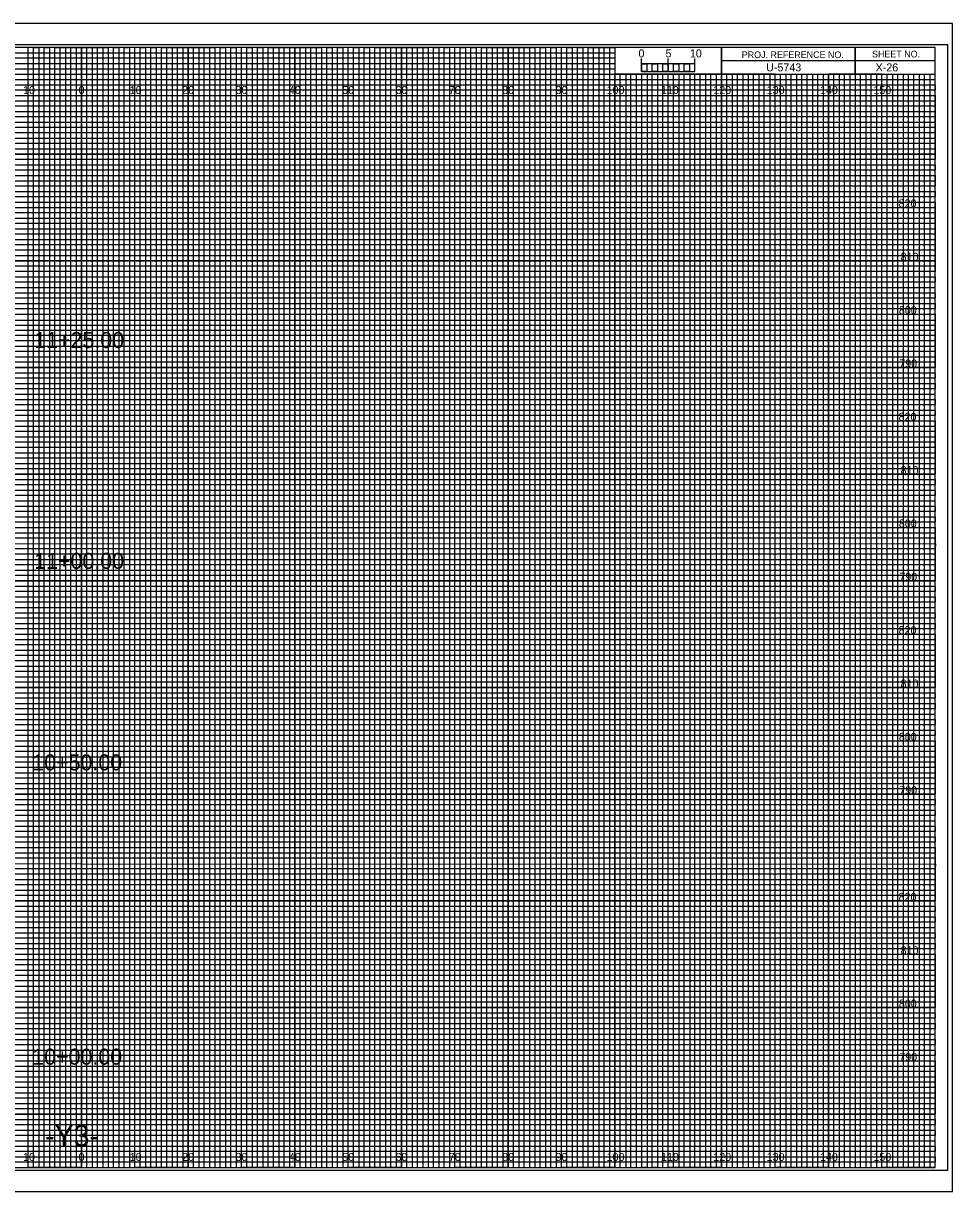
# Model space of a CAD drawing. Extents: x -13 to 323, y -4 to 214.
# Drawn here: x 149.1 to 323.3, y -4.5 to 214.5 of the extents above; entities that cross this region are included whole.
import ezdxf

# ---------------------------------------------------------------- set-up
doc = ezdxf.new("R2010")
doc.units = 0
for name, color, linetype in [('Exist Cross Section Cell', 7, 'Continuous'), ('Exist XS Ground Line', 7, 'Continuous'), ('Prop CMT Conc Surface', 7, 'Continuous'), ('Prop CMT Concrete Structures', 7, 'Continuous'), ('Prop CMT Pvmt Course 1', 7, 'Continuous'), ('Prop CMT Pvmt Course 1 CG', 7, 'Continuous'), ('Prop CMT Pvmt Course 2', 7, 'Continuous'), ('Prop CMT Pvmt Course 3', 7, 'Continuous'), ('Prop CMT Pvmt Surface', 7, 'Continuous'), ('Prop CMT Slope Grass', 7, 'Continuous'), ('Prop CMT Subgrade Earthwork', 7, 'Continuous'), ('Prop XS Hydro Elevations', 7, 'Continuous'), ('Prop XS SE Text', 7, 'Continuous'), ('Prop XS Side Slope Text', 7, 'Continuous'), ('Scratch_Level_4', 7, 'Continuous'), ('Scratch_Level_7', 7, 'Continuous'), ('Scratch_Level_9', 7, 'Continuous')]:
    doc.layers.add(name, color=color, linetype=linetype)

msp = doc.modelspace()

# ---------------------------------------------------------------- linework, layer by layer
at = {"layer": 'Exist XS Ground Line'}
for p, q in [((150, 210), (140, 210)), ((150, 0), (150, 210)), ((170, 210), (160, 210)), ((160, 210), (160, 0)), ((170, 0), (170, 210)), ((190, 210), (180, 210)), ((180, 210), (180, 0)), ((190, 0), (190, 210)), ((210, 210), (200, 210)), ((200, 210), (200, 0)), ((210, 0), (210, 210)), ((230, 210), (220, 210)), ((220, 210), (220, 0)), ((230, 0), (230, 210)), ((250, 210), (240, 210)), ((240, 210), (240, 0)), ((250, 0), (250, 210)), ((260, 210), (260, 0)), ((270, 0), (270, 205)), ((290, 205), (280, 205)), ((280, 205), (280, 0)), ((290, 0), (290, 205)), ((310, 205), (300, 205)), ((300, 205), (300, 0)), ((310, 0), (310, 205)), ((160, 0), (150, 0)), ((180, 0), (170, 0)), ((200, 0), (190, 0)), ((220, 0), (210, 0)), ((240, 0), (230, 0)), ((260, 0), (250, 0)), ((280, 0), (270, 0)), ((300, 0), (290, 0)), ((320, 0), (310, 0)), ((320, 0), (320, 0))]:
    msp.add_line(p, q, dxfattribs=at)
for points in [[(0, 200), (320, 200), (320, 190), (0, 190)], [(0, 180), (320, 180), (320, 170), (0, 170)], [(0, 160), (320, 160), (320, 150), (0, 150)], [(0, 140), (320, 140), (320, 130), (0, 130)], [(0, 120), (320, 120), (320, 110), (0, 110)], [(0, 100), (320, 100), (320, 90), (0, 90)], [(0, 80), (320, 80), (320, 70), (0, 70)], [(0, 60), (320, 60), (320, 50), (0, 50)], [(0, 40), (320, 40), (320, 30), (0, 30)], [(0, 20), (320, 20), (320, 10), (0, 10)]]:
    msp.add_lwpolyline(points, dxfattribs=at)
at = {"layer": 'Prop CMT Conc Surface'}
for p, q in [((323.3, 214.5), (-13.4, 214.5)), ((-13.4, -4.5), (323.3, -4.5))]:
    msp.add_line(p, q, dxfattribs=at)
at = {"layer": 'Prop CMT Concrete Structures'}
for p, q in [((265, 205.49), (265, 207.9)), ((265, 206.9), (265, 207.9)), ((270, 205.49), (270, 207.9)), ((275, 205.49), (275, 207.9)), ((275, 206.9), (275, 207.9))]:
    msp.add_line(p, q, dxfattribs=at)
for points in [[(275, 206.9), (265, 206.9), (265, 205.49), (275, 205.49)], [(265, 206.9), (266, 206.9), (266, 205.49), (265, 205.49)], [(267, 206.9), (268, 206.9), (268, 205.49), (267, 205.49)], [(269, 206.9), (270, 206.9), (270, 205.49), (269, 205.49)], [(271, 206.9), (272, 206.9), (272, 205.49), (271, 205.49)], [(273, 206.9), (274, 206.9), (274, 205.49), (273, 205.49)]]:
    msp.add_lwpolyline(points, close=True, dxfattribs=at)
at = {"layer": 'Prop CMT Pvmt Course 1'}
for p, q in [((150, 0), (150, 210)), ((160, 0), (160, 210)), ((170, 0), (170, 210)), ((180, 0), (180, 210)), ((190, 0), (190, 210)), ((200, 0), (200, 210)), ((210, 0), (210, 210)), ((220, 0), (220, 210)), ((230, 0), (230, 210)), ((240, 0), (240, 210)), ((250, 0), (250, 210)), ((260, 0), (260, 204.69)), ((270, 0), (270, 204.69)), ((280, 0), (280, 204.69)), ((290, 0), (290, 204.69)), ((300, 0), (300, 204.69)), ((310, 0), (310, 204.69)), ((0, 200), (320, 200)), ((0, 190), (320, 190)), ((0, 180), (320, 180)), ((0, 170), (320, 170)), ((0, 160), (320, 160)), ((0, 150), (320, 150)), ((0, 140), (320, 140)), ((0, 130), (320, 130)), ((0, 120), (320, 120)), ((0, 110), (320, 110)), ((0, 100), (320, 100)), ((0, 90), (320, 90)), ((0, 80), (320, 80)), ((0, 70), (320, 70)), ((0, 60), (320, 60)), ((0, 50), (320, 50)), ((0, 40), (320, 40)), ((0, 30), (320, 30)), ((0, 20), (320, 20)), ((0, 10), (320, 10))]:
    msp.add_line(p, q, dxfattribs=at)
at = {"layer": 'Prop CMT Pvmt Course 1 CG'}
msp.add_lwpolyline([(-10.8, -0.5), (322.4, -0.5), (322.4, 210.5), (-10.8, 210.5)], close=True, dxfattribs=at)
at = {"layer": 'Prop CMT Pvmt Course 2'}
for p, q in [((305, 210), (305, 205)), ((305, 205), (305, 210)), ((280, 207.5), (280, 205)), ((320, 207.49), (280, 207.49)), ((280, 205), (320, 205))]:
    msp.add_line(p, q, dxfattribs=at)
for points in [[(320, 210), (0, 210), (0, 0), (320, 0)], [(280, 210), (260, 210), (260, 205.03), (280, 205.03)], [(320, 210), (280, 210), (280, 205), (320, 205)]]:
    msp.add_lwpolyline(points, close=True, dxfattribs=at)
at = {"layer": 'Prop CMT Pvmt Course 3'}
for p, q in [((267, 205), (266.01, 205)), ((266.01, 205), (266.01, 0)), ((267, 0), (267, 205)), ((269, 205), (268, 205)), ((268, 205), (268, 0)), ((269, 0), (269, 205)), ((266.01, 0), (265, 0)), ((268, 0), (267, 0))]:
    msp.add_line(p, q, dxfattribs=at)
for points in [[(150, 0), (151, 0), (151, 210), (152, 210), (152, 0)], [(152, 0), (153, 0), (153, 210), (154, 210), (154, 0)], [(155, 0), (156, 0), (156, 210), (157, 210), (157, 0)], [(157, 0), (158, 0), (158, 210), (159, 210), (159, 0)], [(160, 0), (161, 0), (161, 210), (162, 210), (162, 0)], [(162, 0), (163, 0), (163, 210), (164, 210), (164, 0)], [(165, 0), (166, 0), (166, 210), (167, 210), (167, 0)], [(167, 0), (168, 0), (168, 210), (169, 210), (169, 0)], [(170, 0), (171, 0), (171, 210), (172, 210), (172, 0)], [(172, 0), (173, 0), (173, 210), (174, 210), (174, 0)], [(175, 0), (176, 0), (176, 210), (177, 210), (177, 0)], [(177, 0), (178, 0), (178, 210), (179, 210), (179, 0)], [(180, 0), (181, 0), (181, 210), (182, 210), (182, 0)], [(182, 0), (183, 0), (183, 210), (184, 210), (184, 0)], [(185, 0), (186, 0), (186, 210), (187, 210), (187, 0)], [(187, 0), (188, 0), (188, 210), (189, 210), (189, 0)], [(190, 0), (191, 0), (191, 210), (192, 210), (192, 0)], [(192, 0), (193, 0), (193, 210), (194, 210), (194, 0)], [(195, 0), (196, 0), (196, 210), (197, 210), (197, 0)], [(197, 0), (198, 0), (198, 210), (199, 210), (199, 0)], [(200, 0), (201, 0), (201, 210), (202, 210), (202, 0)], [(202, 0), (203, 0), (203, 210), (204, 210), (204, 0)], [(205, 0), (206, 0), (206, 210), (207, 210), (207, 0)], [(207, 0), (208, 0), (208, 210), (209, 210), (209, 0)], [(210, 0), (211, 0), (211, 210), (212, 210), (212, 0)], [(212, 0), (213, 0), (213, 210), (214, 210), (214, 0)], [(215, 0), (216, 0), (216, 210), (217, 210), (217, 0)], [(217, 0), (218, 0), (218, 210), (219, 210), (219, 0)], [(220, 0), (221, 0), (221, 210), (222, 210), (222, 0)], [(222, 0), (223, 0), (223, 210), (224, 210), (224, 0)], [(225, 0), (226, 0), (226, 210), (227, 210), (227, 0)], [(227, 0), (228, 0), (228, 210), (229, 210), (229, 0)], [(230, 0), (231, 0), (231, 210), (232, 210), (232, 0)], [(232, 0), (233, 0), (233, 210), (234, 210), (234, 0)], [(235, 0), (236, 0), (236, 210), (237, 210), (237, 0)], [(237, 0), (238, 0), (238, 210), (239, 210), (239, 0)], [(240, 0), (241, 0), (241, 210), (242, 210), (242, 0)], [(242, 0), (243, 0), (243, 210), (244, 210), (244, 0)], [(245, 0), (246, 0), (246, 210), (247, 210), (247, 0)], [(247, 0), (248, 0), (248, 210), (249, 210), (249, 0)], [(250, 0), (251, 0), (251, 210), (252, 210), (252, 0)], [(252, 0), (253, 0), (253, 210), (254, 210), (254, 0)], [(255, 0), (256, 0), (256, 210), (257, 210), (257, 0)], [(257, 0), (258, 0), (258, 210), (259, 210), (259, 0)], [(260, 0), (261, 0), (261, 205), (262.02, 205), (262.02, 0)], [(262, 0), (263, 0), (263, 205), (263.99, 205), (263.99, 0)], [(270, 0), (270.98, 0), (270.98, 205), (272, 205), (272, 0)], [(272, 0), (273, 0), (273, 205), (274.05, 205), (274.05, 0)], [(275, 0), (276, 0), (276, 205), (277, 205), (277, 0)], [(277, 0), (278, 0), (278, 205), (279, 205), (279, 0)], [(280, 0), (281, 0), (281, 205), (282, 205), (282, 0)], [(282, 0), (283, 0), (283, 205), (284, 205), (284, 0)], [(285, 0), (286, 0), (286, 205), (287, 205), (287, 0)], [(287, 0), (288, 0), (288, 205), (289, 205), (289, 0)], [(290, 0), (291, 0), (291, 205), (292, 205), (292, 0)], [(292, 0), (293, 0), (293, 205), (294, 205), (294, 0)], [(295, 0), (296, 0), (296, 205), (297, 205), (297, 0)], [(297, 0), (298, 0), (298, 205), (299, 205), (299, 0)], [(300, 0), (301, 0), (301, 205), (302, 205), (302, 0)], [(302, 0), (303, 0), (303, 205), (304, 205), (304, 0)], [(305, 0), (306, 0), (306, 205), (307, 205), (307, 0)], [(307, 0), (308, 0), (308, 205), (309, 205), (309, 0)], [(310, 0), (311, 0), (311, 205), (312, 205), (312, 0)], [(312, 0), (313, 0), (313, 205), (314, 205), (314, 0)], [(315, 0), (316, 0), (316, 205), (317, 205), (317, 0)], [(317, 0), (318, 0), (318, 205), (319, 205), (319, 0)]]:
    msp.add_lwpolyline(points, dxfattribs=at)
at = {"layer": 'Prop CMT Pvmt Surface'}
msp.add_lwpolyline([(-13.4, -4.5), (323.3, -4.5), (323.3, 214.5), (-13.4, 214.5)], close=True, dxfattribs=at)
at = {"layer": 'Scratch_Level_4'}
for points in [[(145, 0), (155, 0), (155, 210), (165, 210), (165, 0), (175, 0), (175, 210), (185, 210), (185, 0), (195, 0), (195, 210), (205, 210), (205, 0), (215, 0), (215, 210), (225, 210), (225, 0), (235, 0), (235, 210), (245, 210), (245, 0), (255, 0), (255, 210), (259.93, 210), (260, 210), (260, 205), (264.99, 205), (264.99, 0), (275, 0), (275, 205), (285, 205), (285, 0), (295, 0), (295, 205), (305, 205), (305, 0), (315, 0), (315, 205)], [(0, 205), (275, 205)], [(0, 185), (320, 185), (320, 195), (0, 195)], [(0, 165), (320, 165), (320, 175), (0, 175)], [(0, 145), (320, 145), (320, 155), (0, 155)], [(0, 125), (320, 125), (320, 135), (0, 135)], [(0, 105), (320, 105), (320, 115), (0, 115)], [(0, 85), (320, 85), (320, 95), (0, 95)], [(0, 65), (320, 65), (320, 75), (0, 75)], [(0, 45), (320, 45), (320, 55), (0, 55)], [(0, 25), (320, 25), (320, 35), (0, 35)], [(0, 5), (320, 5), (320, 15), (0, 15)]]:
    msp.add_lwpolyline(points, dxfattribs=at)
at = {"layer": 'Scratch_Level_7'}
for p, q in [((0, 209), (260, 209)), ((260, 209), (260, 207.98)), ((260, 207.98), (0, 207.98)), ((0, 207), (260, 207)), ((260, 205.89), (0, 205.89)), ((260, 207), (260, 205.89)), ((0, 204), (320, 204))]:
    msp.add_line(p, q, dxfattribs=at)
for points in [[(0, 203), (270, 203), (320, 203), (320, 202), (0, 202)], [(0, 201), (320, 201), (320, 199), (0, 199)], [(0, 198), (320, 198), (320, 197), (0, 196.98)], [(0, 196), (320, 196), (320, 194), (0, 194)], [(0, 193), (320, 193), (320, 192), (0, 192)], [(0, 191), (320, 191), (320, 189), (0, 189)], [(0, 188), (320, 188), (320, 187), (0, 187)], [(0, 186), (320, 186), (320, 184), (0, 184)], [(0, 183), (320, 183), (320, 182), (0, 182)], [(0, 181), (320, 181), (320, 179), (0, 179)], [(0, 178), (320, 178), (320, 177), (0, 177)], [(0, 176), (320, 176), (320, 173.95), (320, 173), (320, 172), (0, 172)], [(0, 174), (320, 174), (320, 173), (0, 173)], [(0, 171), (320, 171), (320, 169), (0, 169.03)], [(0, 169.03), (320, 169), (320, 168), (0, 168)], [(0, 167), (320, 167), (320, 166), (0, 166)], [(0, 164), (320, 164), (320, 163), (0, 163)], [(0, 162), (320, 162), (320, 161), (0, 161)], [(-0.07, 158.89), (320, 158.89), (320, 157.88), (-0.07, 157.88)], [(0, 157), (320, 157), (320, 156), (0, 156)], [(0, 154), (320, 154), (320, 153), (0, 153)], [(0, 152), (320, 152), (320, 151), (0, 151)], [(0, 149), (320, 149), (320, 148), (0, 148)], [(0, 147), (320, 147), (320, 146), (0, 146)], [(0, 144), (320, 144), (320, 143), (0, 143)], [(0, 142), (320, 142), (320, 141), (0, 141)], [(0, 139), (320, 139), (319.99, 137.98), (0, 138)], [(0, 137), (320, 137), (320, 136), (0, 136)], [(0, 134), (320, 134), (320, 133), (0, 133)], [(0, 132), (320, 132), (320, 131), (0, 131)], [(0, 129), (320, 129), (320, 128), (0, 128)], [(0, 127), (320, 127), (320, 126), (0, 126)], [(0, 124), (320, 124), (320, 123), (0, 123)], [(0, 122), (320, 122), (320, 121), (0, 121)], [(0, 119), (320, 119), (320, 118), (0, 118)], [(0, 116.99), (320.07, 116.91), (320, 116), (0, 116)], [(0, 114), (320, 114), (320, 113), (0, 113)], [(0, 112), (320, 112), (320, 111), (0, 111)], [(0, 109), (320, 109), (320, 108), (0, 108)], [(0, 107), (320, 107), (320, 106), (0, 106)], [(0, 104), (320, 104), (320, 103), (0, 103)], [(0, 102), (320, 102), (320, 101), (0, 101)], [(0, 99), (320, 99), (320, 98), (0, 98)], [(0, 97), (320, 97), (320, 96), (0, 96)], [(0, 94), (320, 94), (320, 93), (0, 93)], [(0, 92), (320, 92), (320, 91), (0, 91)], [(0, 89), (320, 89), (320, 88), (0, 88)], [(0, 87), (320, 87), (320, 86), (0, 86)], [(0, 84), (320, 84), (320, 83), (0, 83)], [(0, 82), (320, 82), (320, 81), (0, 81)], [(0, 79), (320, 79), (319.99, 77.98), (0, 78)], [(0, 77), (320, 77), (320, 76), (0, 76)], [(0, 74), (320, 74), (320, 73), (0, 73)], [(0, 72), (320, 72), (320, 71), (0, 71)], [(0, 69), (320, 69), (320, 68), (0, 68)], [(0, 67), (320, 67), (320, 66), (0, 66)], [(0, 64), (320, 64), (320, 63), (0, 63)], [(0, 62), (320, 62), (320, 61), (0, 61)], [(0, 59), (320, 59), (320, 58), (0, 58)], [(0, 56.99), (320.07, 56.91), (320, 56), (0, 56)], [(0, 54), (320, 54), (320, 53), (0, 53)], [(0, 52), (320, 52), (320, 51), (0, 51)], [(0, 49), (320, 49), (320, 48), (0, 48)], [(0, 47), (320, 47), (320, 46), (0, 46)], [(0, 44), (320, 44), (320, 43), (0, 43)], [(0, 42), (320, 42), (320, 41), (0, 41)], [(0, 39), (320, 39), (320, 38), (0, 38)], [(0, 37), (320, 37), (320, 36), (0, 36)], [(0, 34), (320, 34), (320, 33), (0, 33)], [(0, 32), (320, 32), (320, 31), (0, 31)], [(0, 29), (320, 29), (320, 28), (0, 28)], [(0, 27), (320, 27), (320, 26), (0, 26)], [(0, 24), (320, 24), (320, 23), (0, 23)], [(0, 22), (320, 22), (320, 21), (0, 21)], [(0, 19), (320, 19), (320, 18), (0, 18)], [(0, 17), (320, 17), (320, 16), (0, 16)], [(0, 14), (320, 14), (320, 13), (0, 13)], [(0, 12), (320, 12), (320, 11), (0, 11)], [(0, 9), (320, 9), (320, 8), (0, 8)], [(0, 7), (320, 7), (320, 6), (0, 6)], [(0, 4), (320, 4), (320, 3), (0, 3)], [(0, 2), (320, 2), (320, 1), (0, 1)]]:
    msp.add_lwpolyline(points, dxfattribs=at)

# ---------------------------------------------------------------- texts
at = {"layer": 'Exist Cross Section Cell'}
for s, p in [('10', (149.04, 201.25)), ('0', (159.45, 201.25)), ('0', (159.45, 201.25)), ('10', (169.04, 201.25)), ('20', (178.86, 201.25)), ('30', (188.86, 201.25)), ('40', (198.86, 201.25)), ('50', (208.86, 201.25)), ('60', (218.86, 201.25)), ('70', (228.86, 201.25)), ('80', (238.86, 201.25)), ('90', (248.86, 201.25)), ('100', (258.44, 201.25)), ('110', (268.62, 201.25)), ('120', (278.44, 201.25)), ('130', (288.44, 201.25)), ('140', (298.44, 201.25)), ('150', (308.44, 201.25)), ('10', (149.04, 1.25)), ('0', (159.45, 1.25)), ('0', (159.45, 1.25)), ('10', (169.04, 1.25)), ('20', (178.86, 1.25)), ('30', (188.86, 1.25)), ('40', (198.86, 1.25)), ('50', (208.86, 1.25)), ('60', (218.86, 1.25)), ('70', (228.86, 1.25)), ('80', (238.86, 1.25)), ('90', (248.86, 1.25)), ('100', (258.44, 1.25)), ('110', (268.62, 1.25)), ('120', (278.44, 1.25)), ('130', (288.44, 1.25)), ('140', (298.44, 1.25)), ('150', (308.44, 1.25))]:
    msp.add_text(s, height=1.5, dxfattribs=at).set_placement(p)
at = {"layer": 'Prop CMT Concrete Structures'}
msp.add_text('0', height=1.5, dxfattribs=at).set_placement((264.41, 208.12))
at = {"layer": 'Prop CMT Pvmt Course 2'}
for s, p in [('PROJ. REFERENCE NO.', (283.77, 207.99)), ('SHEET NO.', (308.19, 208.12))]:
    msp.add_text(s, height=1.25, dxfattribs=at).set_placement(p)
at = {"layer": 'Prop CMT Slope Grass'}
for s, p in [('11+25.00', (151.13, 153.64)), ('11+00.00', (151.13, 112.24)), ('10+50.00', (150.77, 74.47)), ('10+00.00', (150.77, 19.3))]:
    msp.add_text(s, height=3, dxfattribs=at).set_placement(p)
at = {"layer": 'Prop CMT Subgrade Earthwork'}
for s, p in [('820', (313.17, 180)), ('810', (313.55, 170)), ('800', (313.22, 160)), ('790', (313.3, 150)), ('820', (313.17, 140)), ('810', (313.55, 130)), ('800', (313.22, 120)), ('790', (313.3, 110)), ('820', (313.17, 100)), ('810', (313.55, 90)), ('800', (313.22, 80)), ('790', (313.3, 70)), ('820', (313.17, 50)), ('810', (313.55, 40)), ('800', (313.22, 30)), ('790', (313.3, 20))]:
    msp.add_text(s, height=1.5, dxfattribs=at).set_placement(p)
at = {"layer": 'Prop XS Hydro Elevations'}
msp.add_text('-Y3-', height=4, dxfattribs=at).set_placement((153.17, 4))
at = {"layer": 'Prop XS SE Text'}
msp.add_text('U-5743', height=1.5, dxfattribs=at).set_placement((288.34, 205.5))
at = {"layer": 'Prop XS Side Slope Text'}
msp.add_text('X-26', height=1.5, dxfattribs=at).set_placement((308.86, 205.5))
at = {"layer": 'Scratch_Level_9'}
for s, p in [('5', (269.47, 208.12)), ('10', (274.04, 208.12))]:
    msp.add_text(s, height=1.5, dxfattribs=at).set_placement(p)

doc.saveas('drawing.dxf')
